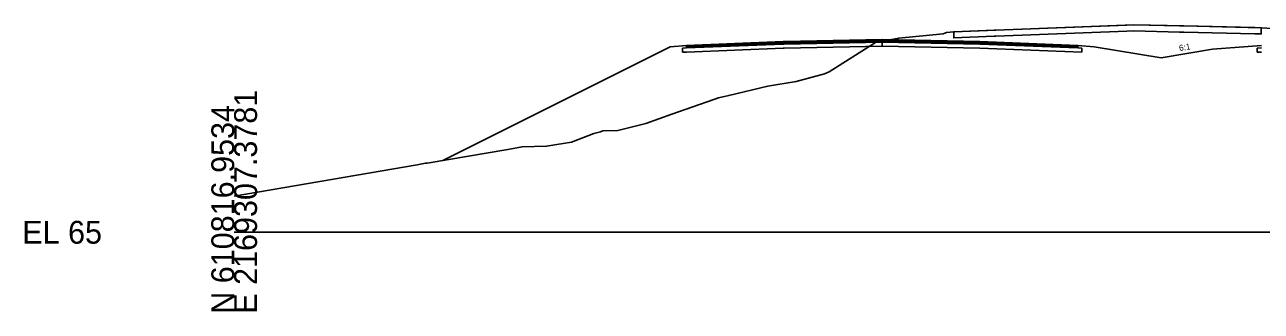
# Model space of a CAD drawing. Extents: x -26 to 1303, y -3010 to 12033.
# Drawn here: x 974.3 to 1126, y 8490.3 to 8525.5 of the extents above; entities that cross this region are included whole.
import ezdxf

# ---------------------------------------------------------------- set-up
doc = ezdxf.new("R2010")
doc.units = 0
for name, color, linetype in [('RD_GPK_XS_Cell', 7, 'Continuous'), ('RD_XS_Base', 7, 'Continuous'), ('RD_XS_ExGround', 7, 'Continuous'), ('RD_XS_ExPaveRet', 7, 'Continuous'), ('RD_XS_Greenside', 7, 'Continuous'), ('RD_XS_Pave', 7, 'Continuous'), ('RD_XS_PaveOvlay_CP', 7, 'Continuous'), ('RD_XS_TieSlope', 7, 'Continuous'), ('RD_XS_TX_Slope', 7, 'Continuous')]:
    doc.layers.add(name, color=color, linetype=linetype)

msp = doc.modelspace()

# ---------------------------------------------------------------- linework, layer by layer
at = {"layer": 'RD_GPK_XS_Cell'}
msp.add_line((1000, 8500), (1150, 8500), dxfattribs=at)
at = {"layer": 'RD_XS_Base'}
for p, q in [((1055.48, 8522.61), (1067.33, 8523.08)), ((1067.33, 8523.08), (1067.48, 8523.09)), ((1067.48, 8523.09), (1079.47, 8523.33)), ((1079.47, 8523.33), (1079.48, 8523.33)), ((1079.48, 8523.48), (1079.48, 8523.49)), ((1079.48, 8523.49), (1079.48, 8523.48)), ((1079.48, 8523.33), (1079.48, 8523.49)), ((1079.48, 8523.49), (1079.48, 8522.83)), ((1079.48, 8523.33), (1079.48, 8523.48)), ((1079.48, 8523.48), (1079.48, 8522.83)), ((1079.48, 8523.33), (1079.48, 8523.33)), ((1079.48, 8523.33), (1079.48, 8522.83)), ((1079.51, 8523.33), (1079.48, 8523.33)), ((1079.48, 8523.33), (1079.48, 8522.83)), ((1091.48, 8523.09), (1079.48, 8523.33)), ((1079.48, 8523.33), (1079.48, 8523.33)), ((1103.48, 8522.61), (1091.48, 8523.09)), ((1093.48, 8523.01), (1093.48, 8523.01)), ((1054.98, 8522.59), (1055.47, 8522.61)), ((1054.98, 8522.57), (1054.98, 8522.59)), ((1054.98, 8522.09), (1054.98, 8522.57)), ((1055.47, 8522.11), (1054.98, 8522.09)), ((1055.47, 8522.61), (1055.48, 8522.61)), ((1055.48, 8522.11), (1055.47, 8522.11)), ((1067.33, 8522.58), (1055.48, 8522.11)), ((1067.48, 8522.59), (1067.33, 8522.58)), ((1079.47, 8522.83), (1067.48, 8522.59)), ((1079.48, 8522.83), (1079.47, 8522.83)), ((1079.48, 8522.83), (1079.51, 8522.83)), ((1079.48, 8522.83), (1079.48, 8522.83)), ((1079.48, 8522.83), (1079.48, 8522.83)), ((1079.48, 8522.83), (1091.48, 8522.59)), ((1091.48, 8522.59), (1103.98, 8522.09)), ((1093.48, 8522.51), (1093.48, 8522.51)), ((1103.98, 8522.59), (1103.48, 8522.61)), ((1103.48, 8522.61), (1103.48, 8522.61)), ((1103.98, 8522.09), (1103.98, 8522.59)), ((1103.98, 8522.59), (1103.98, 8522.59)), ((1103.98, 8522.09), (1103.98, 8522.09)), ((1103.98, 8522.09), (1103.98, 8522.09)), ((1125.5, 8522.59), (1126, 8522.61)), ((1125.5, 8522.09), (1125.5, 8522.59)), ((1125.5, 8522.59), (1125.5, 8522.59)), ((1126, 8522.11), (1125.5, 8522.09)), ((1125.5, 8522.09), (1125.5, 8522.09)), ((1125.5, 8522.09), (1125.5, 8522.09))]:
    msp.add_line(p, q, dxfattribs=at)
at = {"layer": 'RD_XS_ExGround'}
msp.add_lwpolyline([(1000, 8504.43), (1022.44, 8508.29), (1023.46, 8508.47), (1023.66, 8508.49), (1033.55, 8510.15), (1035.32, 8510.49), (1038.32, 8510.54), (1041.39, 8511.06), (1044.13, 8512.12), (1044.94, 8512.32), (1045.23, 8512.43), (1047.06, 8512.49), (1050.51, 8513.33), (1053.68, 8514.5), (1058.83, 8516.29), (1059.42, 8516.49), (1060.67, 8516.79), (1065.48, 8517.91), (1068.92, 8518.49), (1072.4, 8519.45), (1072.97, 8519.68), (1078.68, 8523.26), (1081.52, 8523.81), (1086.98, 8524.34), (1087.38, 8524.5), (1088.28, 8524.59), (1093.44, 8524.8), (1110.36, 8525.46), (1116.51, 8525.3), (1125.98, 8525.08), (1129.46, 8524.85)], dxfattribs=at)
at = {"layer": 'RD_XS_ExPaveRet'}
for points in [[(1125.98, 8525.08), (1125.98, 8525.08), (1125.98, 8524.4), (1125.98, 8524.33), (1125.98, 8524.33), (1125.98, 8524.33), (1125.18, 8524.35), (1116.51, 8524.55), (1115.94, 8524.56), (1110.36, 8524.71), (1109.51, 8524.67), (1093.44, 8524.05), (1093.21, 8524.04), (1088.28, 8523.84), (1088.28, 8523.84), (1088.27, 8523.84), (1088.27, 8524.58), (1088.27, 8524.59), (1088.28, 8524.59), (1088.28, 8524.59), (1093.21, 8524.79), (1093.44, 8524.8), (1109.51, 8525.42), (1110.36, 8525.46), (1115.94, 8525.31), (1116.51, 8525.3), (1125.18, 8525.1), (1125.98, 8525.08), (1125.98, 8525.08)], [(1125.18, 8525.1), (1116.51, 8525.3), (1115.94, 8525.31), (1110.36, 8525.46), (1109.51, 8525.42), (1093.44, 8524.8), (1093.21, 8524.79), (1088.28, 8524.59), (1088.27, 8524.59), (1088.27, 8524.58), (1088.27, 8523.84), (1088.28, 8523.84), (1093.21, 8524.04), (1093.44, 8524.05), (1109.51, 8524.67), (1110.36, 8524.71), (1115.94, 8524.56), (1116.51, 8524.55), (1125.18, 8524.35), (1125.98, 8524.33), (1125.98, 8524.4), (1125.98, 8525.08), (1125.18, 8525.1)]]:
    msp.add_lwpolyline(points, dxfattribs=at)
at = {"layer": 'RD_XS_Greenside'}
for p, q in [((1053.48, 8522.76), (1025.58, 8508.81)), ((1105.48, 8522.76), (1113.7, 8521.39)), ((1120, 8522.44), (1113.7, 8521.39))]:
    msp.add_line(p, q, dxfattribs=at)
at = {"layer": 'RD_XS_Pave'}
for p, q in [((1067.33, 8523.4), (1055.48, 8522.92)), ((1067.33, 8523.24), (1055.48, 8522.77)), ((1055.48, 8522.77), (1067.33, 8523.24)), ((1055.48, 8522.61), (1067.33, 8523.08)), ((1067.48, 8523.4), (1067.33, 8523.4)), ((1067.48, 8523.24), (1067.33, 8523.24)), ((1067.33, 8523.24), (1067.48, 8523.24)), ((1067.33, 8523.08), (1067.48, 8523.09)), ((1079.47, 8523.64), (1067.48, 8523.4)), ((1079.47, 8523.48), (1067.48, 8523.24)), ((1067.48, 8523.24), (1079.47, 8523.48)), ((1067.48, 8523.09), (1079.47, 8523.33)), ((1079.48, 8523.64), (1079.47, 8523.64)), ((1079.48, 8523.49), (1079.47, 8523.48)), ((1079.47, 8523.48), (1079.48, 8523.49)), ((1079.47, 8523.33), (1079.48, 8523.33)), ((1079.51, 8523.64), (1079.48, 8523.64)), ((1091.48, 8523.4), (1079.48, 8523.64)), ((1079.48, 8523.48), (1079.48, 8523.49)), ((1079.48, 8523.49), (1079.51, 8523.48)), ((1079.51, 8523.48), (1079.48, 8523.49)), ((1079.48, 8523.49), (1079.48, 8523.48)), ((1079.48, 8523.33), (1079.48, 8523.49)), ((1079.48, 8523.49), (1091.48, 8523.24)), ((1091.48, 8523.24), (1079.48, 8523.49)), ((1079.48, 8523.49), (1079.48, 8523.33)), ((1079.48, 8523.33), (1079.48, 8523.48)), ((1079.48, 8523.48), (1079.48, 8523.33)), ((1079.48, 8523.33), (1079.51, 8523.33)), ((1079.48, 8523.33), (1079.48, 8523.33)), ((1079.48, 8523.33), (1079.48, 8523.33)), ((1079.48, 8523.33), (1091.48, 8523.09)), ((1103.48, 8522.92), (1091.48, 8523.4)), ((1091.48, 8523.24), (1103.48, 8522.77)), ((1103.48, 8522.77), (1091.48, 8523.24)), ((1091.48, 8523.09), (1103.48, 8522.61)), ((1093.48, 8523.32), (1093.48, 8523.32)), ((1093.48, 8523.16), (1093.48, 8523.16)), ((1093.48, 8523.16), (1093.48, 8523.16)), ((1093.48, 8523.01), (1093.48, 8523.01)), ((1055.48, 8522.92), (1055.48, 8522.92)), ((1055.48, 8522.92), (1055.48, 8522.77)), ((1055.48, 8522.77), (1055.48, 8522.76)), ((1055.48, 8522.76), (1055.48, 8522.61)), ((1103.48, 8522.77), (1103.48, 8522.92)), ((1103.48, 8522.92), (1103.48, 8522.92)), ((1103.48, 8522.77), (1103.48, 8522.77)), ((1103.48, 8522.77), (1103.48, 8522.77)), ((1103.48, 8522.61), (1103.48, 8522.77)), ((1103.48, 8522.77), (1103.48, 8522.77)), ((1103.48, 8522.61), (1103.48, 8522.61)), ((1103.48, 8522.61), (1103.48, 8522.61))]:
    msp.add_line(p, q, dxfattribs=at)
at = {"layer": 'RD_XS_PaveOvlay_CP'}
for p, q in [((1055.48, 8522.92), (1067.48, 8523.4)), ((1067.48, 8523.4), (1079.48, 8523.64)), ((1079.48, 8523.64), (1091.48, 8523.4)), ((1091.48, 8523.4), (1103.48, 8522.92))]:
    msp.add_line(p, q, dxfattribs=at)
at = {"layer": 'RD_XS_TieSlope'}
for p, q in [((1055.48, 8522.92), (1053.48, 8522.76)), ((1103.48, 8522.92), (1105.48, 8522.76)), ((1126, 8522.92), (1120, 8522.44))]:
    msp.add_line(p, q, dxfattribs=at)

# ---------------------------------------------------------------- texts
at = {"layer": 'RD_GPK_XS_Cell'}
for s, p in [('E 2169307.3781', (1002.8, 8490)), ('N 610816.9534', (1000, 8490))]:
    msp.add_text(s, height=2.8, rotation=90, dxfattribs=at).set_placement(p)
msp.add_text('EL 65', height=2.8, dxfattribs=at).set_placement((974, 8498.6))
at = {"layer": 'RD_XS_TX_Slope'}
msp.add_text('6:1', height=0.75, rotation=9.4642, dxfattribs=at).set_placement((1115.97, 8522.21))

doc.saveas('drawing.dxf')
